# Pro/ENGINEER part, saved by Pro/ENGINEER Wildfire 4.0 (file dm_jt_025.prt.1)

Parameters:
  METRIC = "NO"

Other parameters: PITCH, DRILL_POINT_ANGLE, DRILL_DEPTH, DRILL_DIAMETER, THREAD_DIAMETER, THREADS_PER_INCH, THREAD_DEPTH, THREAD_LENGTH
